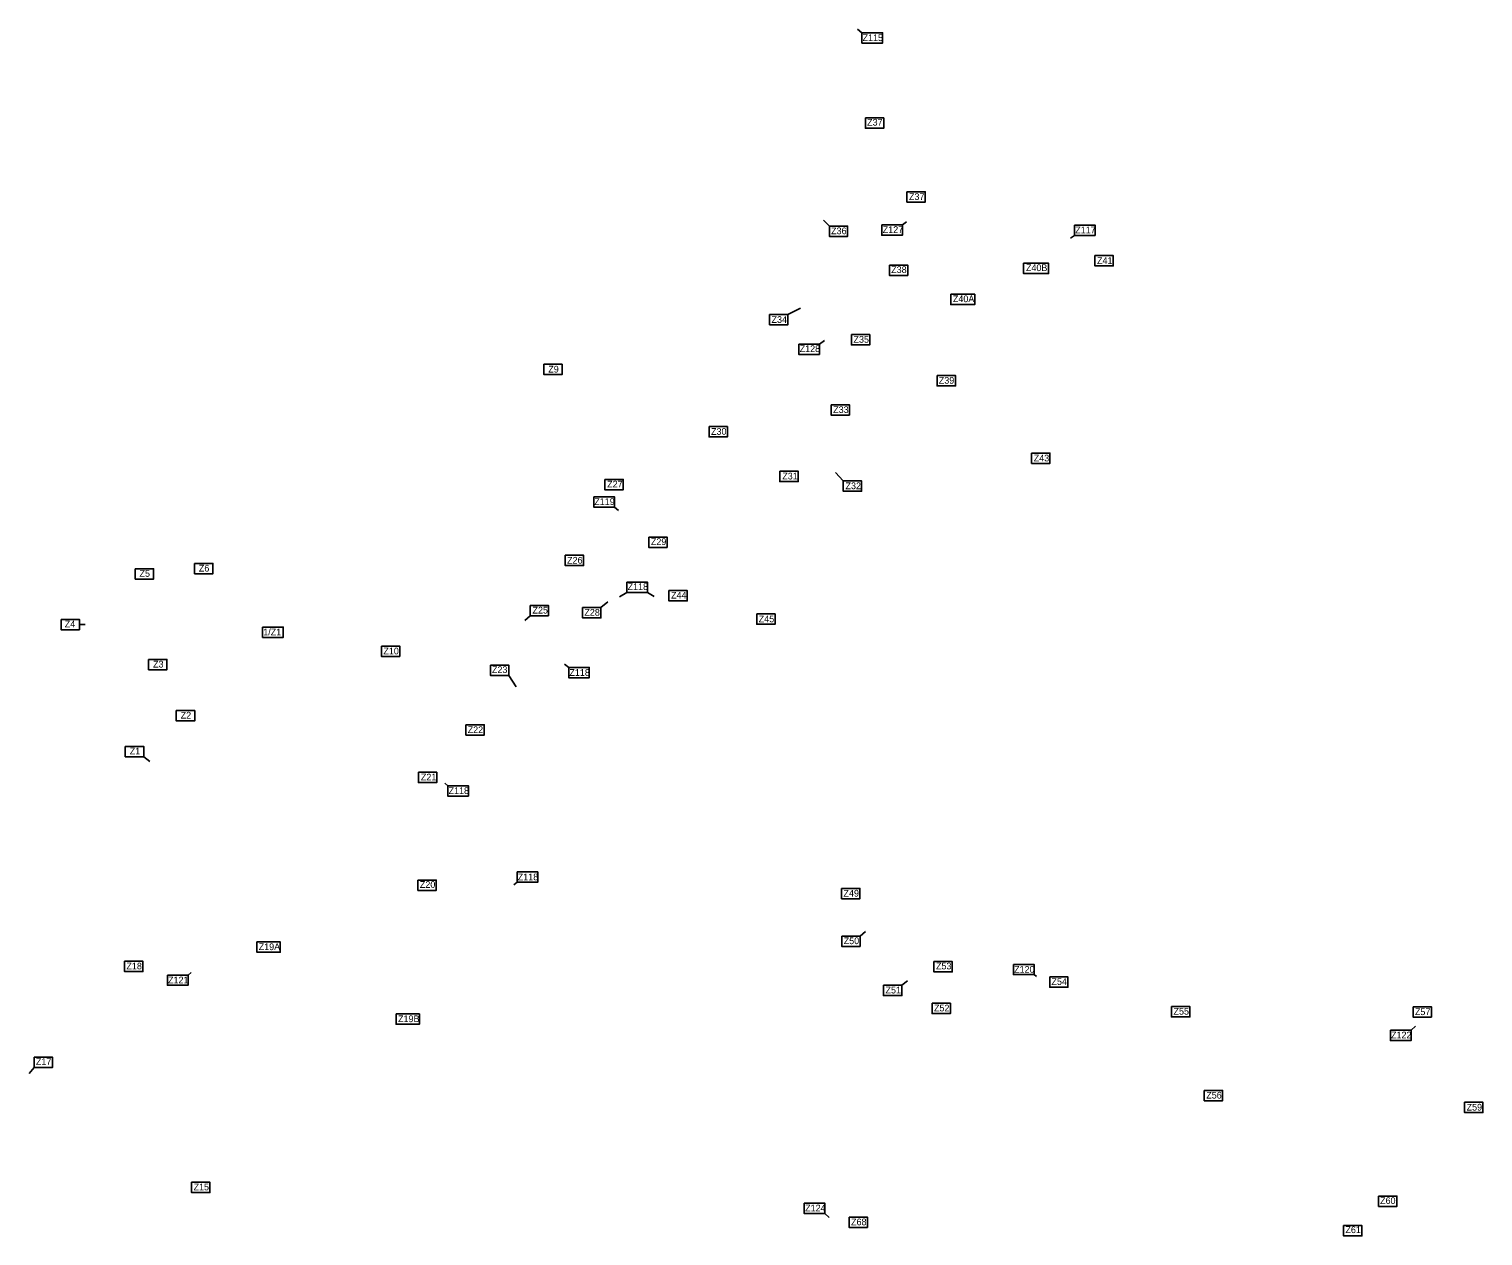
# Model space of a CAD drawing. Extents: x -443483 to -438117, y -1133472 to -1129797.
# Drawn here: x -443022 to -440855, y -1131596 to -1129797 of the extents above; entities that cross this region are included whole.
import ezdxf

# ---------------------------------------------------------------- set-up
doc = ezdxf.new("R2010")
doc.units = 0
doc.layers.add('Vrstva 3', color=7, linetype='Continuous')
doc.layers.add('Vrstva 8', color=7, linetype='Continuous')

msp = doc.modelspace()

# ---------------------------------------------------------------- linework, layer by layer
at = {"layer": 'Vrstva 3'}
for p, q in [((-441780.6, -1129802.1), (-441787.2, -1129796.7)), ((-441829.1, -1130090.3), (-441838, -1130081.7)), ((-441808.5, -1130470.4), (-441819.7, -1130457.7)), ((-442169.8, -1130659.1), (-442159.4, -1130650.4)), ((-442947.3, -1130684.5), (-442938.5, -1130684.6)), ((-442275.3, -1130671.3), (-442283.1, -1130678.3)), ((-442307.2, -1130760.3), (-442296.3, -1130777.1)), ((-442851.5, -1130881.4), (-442842.3, -1130888.4)), ((-441783.2, -1131148.9), (-441775.1, -1131141.9)), ((-441721, -1131222.3), (-441712.8, -1131215.4)), ((-443014.7, -1131344.8), (-443022.4, -1131353.5))]:
    msp.add_line(p, q, dxfattribs=at)
for points in [[(-441780.6, -1129802.1), (-441749.8, -1129802.1), (-441749.8, -1129817.5), (-441780.6, -1129817.5)], [(-441775.4, -1129929), (-441748, -1129929), (-441748, -1129944.4), (-441775.4, -1129944.4)], [(-441713.5, -1130039.3), (-441686.2, -1130039.3), (-441686.2, -1130054.7), (-441713.5, -1130054.7)], [(-441829.1, -1130090.3), (-441801.8, -1130090.3), (-441801.8, -1130105.7), (-441829.1, -1130105.7)], [(-441539.4, -1130145.7), (-441502.1, -1130145.7), (-441502.1, -1130161.1), (-441539.4, -1130161.1)], [(-441433.1, -1130134.4), (-441405.7, -1130134.4), (-441405.7, -1130149.8), (-441433.1, -1130149.8)], [(-441739.6, -1130148.5), (-441712.2, -1130148.5), (-441712.2, -1130163.9), (-441739.6, -1130163.9)], [(-441648.2, -1130192), (-441612.4, -1130192), (-441612.4, -1130207.4), (-441648.2, -1130207.4)], [(-441918.2, -1130222.1), (-441890.9, -1130222.1), (-441890.9, -1130237.5), (-441918.2, -1130237.5)], [(-441796.3, -1130252.1), (-441768.9, -1130252.1), (-441768.9, -1130267.5), (-441796.3, -1130267.5)], [(-442254.8, -1130296.3), (-442227.5, -1130296.3), (-442227.5, -1130311.7), (-442254.8, -1130311.7)], [(-441668.4, -1130313.2), (-441641, -1130313.2), (-441641, -1130328.6), (-441668.4, -1130328.6)], [(-441826.6, -1130356.8), (-441799.2, -1130356.8), (-441799.2, -1130372.2), (-441826.6, -1130372.2)], [(-442008.5, -1130389.3), (-441981.2, -1130389.3), (-441981.2, -1130404.7), (-442008.5, -1130404.7)], [(-441527.5, -1130428.9), (-441500.2, -1130428.9), (-441500.2, -1130444.3), (-441527.5, -1130444.3)], [(-442163.9, -1130468.1), (-442136.5, -1130468.1), (-442136.5, -1130483.5), (-442163.9, -1130483.5)], [(-441903, -1130455.8), (-441875.6, -1130455.8), (-441875.6, -1130471.2), (-441903, -1130471.2)], [(-441808.5, -1130470.4), (-441781.1, -1130470.4), (-441781.1, -1130485.8), (-441808.5, -1130485.8)], [(-442098.4, -1130554.1), (-442071.1, -1130554.1), (-442071.1, -1130569.5), (-442098.4, -1130569.5)], [(-442864.1, -1130601.3), (-442836.8, -1130601.3), (-442836.8, -1130616.7), (-442864.1, -1130616.7)], [(-442775.7, -1130593.4), (-442748.3, -1130593.4), (-442748.3, -1130608.8), (-442775.7, -1130608.8)], [(-442222.8, -1130581.2), (-442195.5, -1130581.2), (-442195.5, -1130596.5), (-442222.8, -1130596.5)], [(-442068.4, -1130633.9), (-442041.1, -1130633.9), (-442041.1, -1130649.3), (-442068.4, -1130649.3)], [(-442275.3, -1130655.9), (-442247.9, -1130655.9), (-442247.9, -1130671.3), (-442275.3, -1130671.3)], [(-442197.1, -1130659.1), (-442169.8, -1130659.1), (-442169.8, -1130674.5), (-442197.1, -1130674.5)], [(-442974.7, -1130676.8), (-442947.3, -1130676.8), (-442947.3, -1130692.2), (-442974.7, -1130692.2)], [(-441937.3, -1130668.5), (-441909.9, -1130668.5), (-441909.9, -1130683.9), (-441937.3, -1130683.9)], [(-442497.1, -1130716.5), (-442469.7, -1130716.5), (-442469.7, -1130731.9), (-442497.1, -1130731.9)], [(-442844.2, -1130736.3), (-442816.9, -1130736.3), (-442816.9, -1130751.7), (-442844.2, -1130751.7)], [(-442334.6, -1130744.9), (-442307.2, -1130744.9), (-442307.2, -1130760.3), (-442334.6, -1130760.3)], [(-442802.8, -1130812.7), (-442775.4, -1130812.7), (-442775.4, -1130828.1), (-442802.8, -1130828.1)], [(-442370.9, -1130833.9), (-442343.6, -1130833.9), (-442343.6, -1130849.2), (-442370.9, -1130849.2)], [(-442878.9, -1130866.1), (-442851.5, -1130866.1), (-442851.5, -1130881.4), (-442878.9, -1130881.4)], [(-442441.8, -1130904.7), (-442414.5, -1130904.7), (-442414.5, -1130920.1), (-442441.8, -1130920.1)], [(-442442.5, -1131065.5), (-442415.2, -1131065.5), (-442415.2, -1131080.9), (-442442.5, -1131080.9)], [(-441810.9, -1131077.7), (-441783.5, -1131077.7), (-441783.5, -1131093.1), (-441810.9, -1131093.1)], [(-442682.6, -1131157.6), (-442647.9, -1131157.6), (-442647.9, -1131173), (-442682.6, -1131173)], [(-441810.6, -1131148.9), (-441783.2, -1131148.9), (-441783.2, -1131164.3), (-441810.6, -1131164.3)], [(-442879.9, -1131186.4), (-442852.5, -1131186.4), (-442852.5, -1131201.8), (-442879.9, -1131201.8)], [(-441673.2, -1131186.9), (-441645.8, -1131186.9), (-441645.8, -1131202.2), (-441673.2, -1131202.2)], [(-441748.4, -1131222.3), (-441721, -1131222.3), (-441721, -1131237.7), (-441748.4, -1131237.7)], [(-441500.6, -1131209.7), (-441473.3, -1131209.7), (-441473.3, -1131225.1), (-441500.6, -1131225.1)], [(-441676, -1131249.1), (-441648.6, -1131249.1), (-441648.6, -1131264.5), (-441676, -1131264.5)], [(-442475.1, -1131264.8), (-442440.3, -1131264.8), (-442440.3, -1131280.2), (-442475.1, -1131280.2)], [(-441319, -1131254), (-441291.6, -1131254), (-441291.6, -1131269.4), (-441319, -1131269.4)], [(-440958.8, -1131254.3), (-440931.4, -1131254.3), (-440931.4, -1131269.7), (-440958.8, -1131269.7)], [(-443014.7, -1131329.4), (-442987.3, -1131329.4), (-442987.3, -1131344.8), (-443014.7, -1131344.8)], [(-441270.2, -1131379), (-441242.8, -1131379), (-441242.8, -1131394.4), (-441270.2, -1131394.4)], [(-440882, -1131396.5), (-440854.6, -1131396.5), (-440854.6, -1131411.9), (-440882, -1131411.9)], [(-442780, -1131515.9), (-442752.6, -1131515.9), (-442752.6, -1131531.3), (-442780, -1131531.3)], [(-441010.2, -1131536.4), (-440982.9, -1131536.4), (-440982.9, -1131551.8), (-441010.2, -1131551.8)], [(-441799.8, -1131567.7), (-441772.4, -1131567.7), (-441772.4, -1131583.1), (-441799.8, -1131583.1)], [(-441062.3, -1131580.5), (-441035, -1131580.5), (-441035, -1131595.9), (-441062.3, -1131595.9)]]:
    msp.add_lwpolyline(points, close=True, dxfattribs=at)
at = {"layer": 'Vrstva 8'}
for p, q in [((-441720.1, -1130088.6), (-441714.3, -1130084)), ((-441463.6, -1130104.2), (-441469.4, -1130108.5)), ((-441890.9, -1130222.1), (-441872.3, -1130212.6)), ((-441844, -1130266.2), (-441836.1, -1130260.9)), ((-442149.3, -1130509.6), (-442143.6, -1130514.2)), ((-442131, -1130636.5), (-442142.2, -1130643.1)), ((-442100.3, -1130636.5), (-442090.5, -1130642.7)), ((-442217.8, -1130748.4), (-442224.2, -1130743.6)), ((-442398, -1130924.7), (-442402.3, -1130921.1)), ((-442294.8, -1131068.6), (-442299.8, -1131072.4)), ((-442785.3, -1131206.9), (-442780.8, -1131203.4)), ((-441523.9, -1131206.4), (-441520.2, -1131209.2)), ((-440961.7, -1131289.2), (-440954.9, -1131283.1)), ((-441835.8, -1131562.7), (-441829.5, -1131568.4))]:
    msp.add_line(p, q, dxfattribs=at)
for points in [[(-441750.9, -1130088.6), (-441720.1, -1130088.6), (-441720.1, -1130104), (-441750.9, -1130104)], [(-441463.6, -1130088.8), (-441432.8, -1130088.8), (-441432.8, -1130104.2), (-441463.6, -1130104.2)], [(-441463.6, -1130088.8), (-441432.8, -1130088.8), (-441432.8, -1130104.2), (-441463.6, -1130104.2)], [(-441874.8, -1130266.2), (-441844, -1130266.2), (-441844, -1130281.6), (-441874.8, -1130281.6)], [(-442180.1, -1130494.2), (-442149.3, -1130494.2), (-442149.3, -1130509.6), (-442180.1, -1130509.6)], [(-442131, -1130621.1), (-442100.3, -1130621.1), (-442100.3, -1130636.5), (-442131, -1130636.5)], [(-442674.2, -1130688.2), (-442643.4, -1130688.2), (-442643.4, -1130703.5), (-442674.2, -1130703.5)], [(-442217.8, -1130748.4), (-442187, -1130748.4), (-442187, -1130763.8), (-442217.8, -1130763.8)], [(-442398, -1130924.7), (-442367.2, -1130924.7), (-442367.2, -1130940.1), (-442398, -1130940.1)], [(-442294.8, -1131053.2), (-442264, -1131053.2), (-442264, -1131068.6), (-442294.8, -1131068.6)], [(-442816.1, -1131206.9), (-442785.3, -1131206.9), (-442785.3, -1131222.3), (-442816.1, -1131222.3)], [(-441554.7, -1131191), (-441523.9, -1131191), (-441523.9, -1131206.4), (-441554.7, -1131206.4)], [(-440992.5, -1131289.2), (-440961.7, -1131289.2), (-440961.7, -1131304.6), (-440992.5, -1131304.6)], [(-441866.6, -1131547.3), (-441835.8, -1131547.3), (-441835.8, -1131562.7), (-441866.6, -1131562.7)]]:
    msp.add_lwpolyline(points, close=True, dxfattribs=at)

# ---------------------------------------------------------------- texts
at = {"layer": 'Vrstva 3'}
for s, p in [('Z115', (-441779.6, -1129814.6)), ('Z37', (-441772.8, -1129940.6)), ('Z37', (-441710.4, -1130051.5)), ('Z36', (-441826.5, -1130102.5)), ('Z41', (-441430, -1130146.8)), ('Z38', (-441736.9, -1130160.4)), ('Z40B', (-441536, -1130157.5)), ('Z40A', (-441644.9, -1130203.8)), ('Z34', (-441915.3, -1130234.7)), ('Z35', (-441793.1, -1130264.3)), ('Z9', (-442248.2, -1130308.7)), ('Z39', (-441665.9, -1130325.4)), ('Z33', (-441823.4, -1130369)), ('Z30', (-442005.5, -1130401.6)), ('Z43', (-441524.3, -1130441.2)), ('Z27', (-442160.4, -1130480.1)), ('Z31', (-441899.3, -1130468.1)), ('Z32', (-441805, -1130482.6)), ('Z29', (-442095.2, -1130565.8)), ('Z6', (-442769.2, -1130605.4)), ('Z26', (-442220.1, -1130593.6)), ('Z5', (-442857.7, -1130613.2)), ('Z44', (-442065.1, -1130645.7)), ('Z25', (-442271.7, -1130668)), ('Z28', (-442194.4, -1130671.3)), ('Z4', (-442969.1, -1130688.5)), ('Z45', (-441934.4, -1130681)), ('Z10', (-442494.1, -1130728.9)), ('Z3', (-442837.5, -1130748.5)), ('Z23', (-442332.2, -1130756.7)), ('Z2', (-442796.3, -1130824.6)), ('Z22', (-442368.4, -1130846.3)), ('Z1', (-442872.3, -1130878.1)), ('Z21', (-442438.2, -1130916.8)), ('Z20', (-442439.7, -1131077)), ('Z49', (-441808, -1131090)), ('Z19A', (-442680, -1131169.8)), ('Z50', (-441807.7, -1131160.9)), ('Z18', (-442877.2, -1131198.5)), ('Z53', (-441670.1, -1131198.5)), ('Z51', (-441745.4, -1131234.4)), ('Z54', (-441497.9, -1131221.7)), ('Z52', (-441673.1, -1131261.1)), ('Z19B', (-442472.2, -1131277.2)), ('Z55', (-441315.9, -1131266)), ('Z57', (-440956, -1131266.7)), ('Z17', (-443012.2, -1131341)), ('Z56', (-441267.1, -1131391.1)), ('Z59', (-440878.9, -1131409)), ('Z15', (-442777.1, -1131528)), ('Z60', (-441007.9, -1131548.3)), ('Z68', (-441796.7, -1131580)), ('Z61', (-441059.6, -1131591.7))]:
    msp.add_text(s, height=10, dxfattribs=at).set_placement(p)
at = {"layer": 'Vrstva 8'}
for s, p in [('Z127', (-441749.5, -1130100.6)), ('Z117', (-441462.5, -1130101.2)), ('Z128', (-441873.4, -1130278.2)), ('Z119', (-442179.6, -1130506.2)), ('Z118', (-442129.9, -1130632.9)), ('1/Z1', (-442673.2, -1130700.6)), ('Z118', (-442216.7, -1130760.9)), ('Z118', (-442396.9, -1130937.1)), ('Z118', (-442293.7, -1131065.7)), ('Z120', (-441553.6, -1131203.5)), ('Z121', (-442815.1, -1131219.3)), ('Z122', (-440991.6, -1131301.3)), ('Z124', (-441865.2, -1131559.3))]:
    msp.add_text(s, height=10, dxfattribs=at).set_placement(p)

doc.saveas('drawing.dxf')
